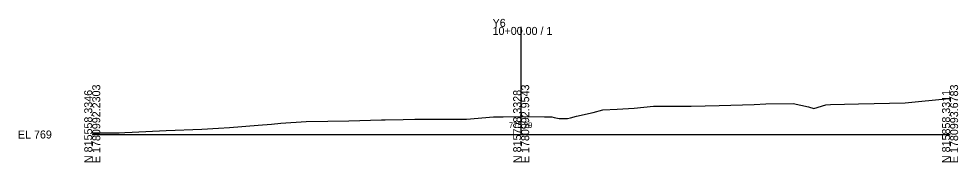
# Model space of a CAD drawing. Extents: x -26 to 1603, y -10 to 6024.
# Drawn here: x -25.7 to 302.8, y -9.7 to 40.5 of the extents above; entities that cross this region are included whole.
import ezdxf

# ---------------------------------------------------------------- set-up
doc = ezdxf.new("R2010")
doc.units = 0
for name, color, linetype in [('Exist Cross Section Cell', 7, 'Continuous'), ('Exist XS Center Line Elevation Label', 7, 'Continuous'), ('Exist XS Ground Line', 7, 'Continuous')]:
    doc.layers.add(name, color=color, linetype=linetype)

msp = doc.modelspace()

# ---------------------------------------------------------------- linework, layer by layer
at = {"layer": 'Exist Cross Section Cell'}
for p, q in [((150, 0), (150, 37.64)), ((0, 0), (150, 0)), ((150, 0), (300, 0))]:
    msp.add_line(p, q, dxfattribs=at)
at = {"layer": 'Exist XS Ground Line'}
for p, q in [((189.46, 9.24), (196.24, 9.89)), ((196.24, 9.89), (196.54, 9.93)), ((196.54, 9.93), (197.59, 9.93)), ((197.59, 9.93), (206.3, 9.89)), ((206.3, 9.89), (209.43, 9.91)), ((209.43, 9.91), (219.25, 10.2)), ((219.25, 10.2), (231.44, 10.54)), ((231.44, 10.54), (235.62, 10.68)), ((235.62, 10.68), (245.07, 10.82)), ((245.07, 10.82), (250.45, 9.64)), ((252.31, 9.14), (256.55, 10.4)), ((256.55, 10.4), (258.2, 10.53)), ((258.2, 10.53), (267.99, 10.74)), ((267.99, 10.74), (284.29, 11.1)), ((284.29, 11.1), (299.58, 12.54)), ((299.58, 12.54), (300, 12.55)), ((169.32, 6.37), (175.13, 7.75)), ((175.13, 7.75), (178.61, 8.65)), ((178.61, 8.65), (183.56, 8.92)), ((183.56, 8.92), (189.46, 9.24)), ((250.45, 9.64), (252.31, 9.14)), ((48.04, 2.4), (58.08, 3.29)), ((58.08, 3.29), (62.63, 3.64)), ((62.63, 3.64), (65.93, 3.92)), ((65.93, 3.92), (74.8, 4.59)), ((74.8, 4.59), (82.44, 4.71)), ((82.44, 4.71), (89.69, 4.82)), ((89.69, 4.82), (101.1, 5.1)), ((101.1, 5.1), (101.48, 5.1)), ((101.48, 5.1), (102.46, 5.14)), ((102.46, 5.14), (108.74, 5.29)), ((108.74, 5.29), (112.85, 5.31)), ((112.85, 5.31), (130.93, 5.34)), ((130.93, 5.34), (140.31, 6.22)), ((140.31, 6.22), (143.75, 6.22)), ((143.75, 6.22), (150, 6.29)), ((150, 6.29), (150.32, 6.29)), ((150.32, 6.29), (158.19, 6.17)), ((158.19, 6.17), (160.69, 6.13)), ((160.69, 6.13), (161.56, 5.93)), ((161.56, 5.93), (163.32, 5.61)), ((163.32, 5.61), (165.52, 5.62)), ((165.52, 5.62), (166.21, 5.55)), ((166.21, 5.55), (167.26, 5.83)), ((167.26, 5.83), (169.32, 6.37)), ((0, 0.53), (9.38, 0.63)), ((9.38, 0.63), (11.35, 0.68)), ((11.35, 0.68), (13.96, 0.82)), ((13.96, 0.82), (25.9, 1.36)), ((25.9, 1.36), (38.35, 1.91)), ((38.35, 1.91), (44.11, 2.22)), ((44.11, 2.22), (48.04, 2.4))]:
    msp.add_line(p, q, dxfattribs=at)

# ---------------------------------------------------------------- texts
at = {"layer": 'Exist Cross Section Cell'}
for s, p in [('Y6', (140, 37.64)), ('10+00.00 / 1', (140, 34.84)), ('EL 769', (-26, -1.4))]:
    msp.add_text(s, height=2.8, dxfattribs=at).set_placement(p)
for s, p in [('E 1780992.2303', (2.8, -10)), ('E 1780992.9543', (152.8, -10)), ('E 1780993.6783', (302.8, -10)), ('N 815558.3346', (0, -10)), ('N 815708.3328', (150, -10)), ('N 815858.3311', (300, -10))]:
    msp.add_text(s, height=2.8, rotation=90, dxfattribs=at).set_placement(p)
at = {"layer": 'Exist XS Center Line Elevation Label'}
msp.add_text('775.29', height=2, dxfattribs=at).set_placement((145.73, 2.29))

doc.saveas('drawing.dxf')
